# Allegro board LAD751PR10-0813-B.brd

Outline 338.42 x 185.75 mm; copper layers: TOP, GND1, IN1, GND2, IN2, GND3, IN3, IN4, GND4, IN5, GND5, IN6, GND6, BOTTOM. Coordinates in mm from the lower left corner of the outline.

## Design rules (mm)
net group CSO_1: nets CSON_1 CSOP_1
net group CSS_2: nets CSSN_2 CSSP_2
net group CSS_B+: nets CSSN_B+ CSSP_B+
net group CSSUM: nets CSNSUM CSPSUM
net group DDR-ALERT: nets DDR_A_ALERT# DDR_B_ALERT#
net group DDRB-CLK: nets M_CLK_DDR2 M_CLK_DDR#2
net group DIFFPAIR29: nets FBB_CLK0 FBB_CLK0#
net group DIFFPAIR50: nets M_CLK_DDR3 M_CLK_DDR#3
net group DIFFPAIR70: nets CSSN_1 CSSP_1
net group DIFFPAIR85: nets TP_CLK TP_DATA
net group DIFFPAIR150: nets HDMI_CTRLCLK HDMI_CTRLDAT
net group DIFFPAIR158: nets FBA_WCK45 FBA_WCK45#
net group DIFFPAIR159: nets FBA_WCK67 FBA_WCK67#
net group DIFFPAIR160: nets FBA_WCK23 FBA_WCK23#
net group DIFFPAIR161: nets FBA_WCK01 FBA_WCK01#
net group DIFFPAIR162: nets FBB_WCK45 FBB_WCK45#
net group DIFFPAIR163: nets FBB_WCK67 FBB_WCK67#
net group DIFFPAIR164: nets FBB_WCK23 FBB_WCK23#
net group DIFFPAIR165: nets FBB_WCK01 FBB_WCK01#
net group DIFFPAIR166: nets FBC_WCK45 FBC_WCK45#
net group DIFFPAIR167: nets FBC_WCK67 FBC_WCK67#
net group DIFFPAIR168: nets FBC_WCK23 FBC_WCK23#
net group DIFFPAIR169: nets FBC_WCK01 FBC_WCK01#
net group DIFFPAIR170: nets FBD_WCK45 FBD_WCK45#
net group DIFFPAIR171: nets FBD_WCK67 FBD_WCK67#
net group DIFFPAIR172: nets FBD_WCK01 FBD_WCK01#
net group DIFFPAIR173: nets FBD_WCK23 FBD_WCK23#
net group DIFFPAIR174: nets CPU_EDP_TX3N CPU_EDP_TX3P
net group DIFFPAIR175: nets CPU_EDP_TX2N CPU_EDP_TX2P
net group DIFFPAIR176: nets VGA_SMB_CK2 VGA_SMB_DA2
net group DIFFPAIR178: nets USB20_N9 USB20_P9
net group DIFFPAIR179: nets USB20_N9_L USB20_P9_L
net group DIFFPAIR180: nets TBTA_LSRX TBTA_LSTX
net group DIFFPAIR181: nets XTALIN XTALOUT
net group DIFFPAIR182: nets MDP_AUX#_SDA MDP_AUX_SCL
net group DIFFPAIR183: nets PCIE_PTX_DRX_N19_C PCIE_PTX_DRX_P19_C
net group DIFFPAIR184: nets PCIE_PTX_DRX_N20_C PCIE_PTX_DRX_P20_C
net group DIFFPAIR185: nets PCIE_PTX_DRX_N18_C PCIE_PTX_DRX_P18_C
net group DIFFPAIR186: nets PCIE_PTX_DRX_N13_C PCIE_PTX_DRX_P13_C
net group DIFFPAIR187: nets PCIE_PTX_DRX_N14_C PCIE_PTX_DRX_P14_C
net group DIFFPAIR188: nets PCIE_PTX_DRX_N11_C PCIE_PTX_DRX_P11_C
net group DIFFPAIR189: nets PCIE_PTX_DRX_N10_C PCIE_PTX_DRX_P10_C
net group DIFFPAIR190: nets PCIE_PTX_DRX_N12_C PCIE_PTX_DRX_P12_C
net group DIFFPAIR191: nets PCIE_PTX_DRX_N9_C PCIE_PTX_DRX_P9_C
net group DIFFPAIR192: nets PCIE_PTX_DRX_N17_C PCIE_PTX_DRX_P17_C
net group DP18: nets FBA_CLK1 FBA_CLK1#
net group FBA-CLK: nets FBA_CLK0 FBA_CLK0#
net group FBB-CLK: nets FBB_CLK1 FBB_CLK1#
net group FBC-CLK: nets FBC_CLK0 FBC_CLK0#
net group FBC_CLK1: nets FBC_CLK1 FBC_CLK1#
net group I2C0__EC: nets I2C0_SCL_EC I2C0_SDA_EC
net group I2CC_: nets I2CC_SCL I2CC_SDA
net group I2CC__R: nets I2CC_SCL_R I2CC_SDA_R
net group ISUM_GT: nets ISUMN_GT ISUMP_GT
net group ISUM_SA: nets ISUMN_SA ISUMP_SA
net group ISUM_VCORE: nets ISUMN_VCORE ISUMP_VCORE
net group NVVDD_ISUM1: nets NVVDD_ISUMN1 NVVDD_ISUMP1
net group NVVDD_ISUM2: nets NVVDD_ISUMN2 NVVDD_ISUMP2
net group NVVDD_ISUM3: nets NVVDD_ISUMN3 NVVDD_ISUMP3
net group NVVDD_ISUM4: nets NVVDD_ISUMN4 NVVDD_ISUMP4
net group PCIE_PRX_DTX_13: nets PCIE_PRX_DTX_N13 PCIE_PRX_DTX_P13
net group PCIE_PRX_DTX_14: nets PCIE_PRX_DTX_N14 PCIE_PRX_DTX_P14
net group PCIE_PTX_DRX_13: nets PCIE_PTX_DRX_N13 PCIE_PTX_DRX_P13
net group PCIE_PTX_DRX_14: nets PCIE_PTX_DRX_N14 PCIE_PTX_DRX_P14
net group SATA_PRX_DTX_3: nets SATA_PRX_DTX_N3 SATA_PRX_DTX_P3
net group SATA_PTX_DRX_3: nets SATA_PTX_DRX_N3 SATA_PTX_DRX_P3
net group SPK_L_CONN: nets SPK_L+_CONN SPK_L-_CONN
net group SPK_R_CONN: nets SPK_R+_CONN SPK_R-_CONN
net group TMDS_F: nets TMDS_SCLF TMDS_SDAF
net group USB3R3_C: nets USB3RN3_C USB3RP3_C
net group VIN1: nets VIN1N VIN1P
net group VIN2: nets VIN2N VIN2P
net group VIN3: nets VIN3N VIN3P
net group 12: nets DGPU_PEX_RST#
net group ASYNCHRONOUS: nets CALDERA_RST# CDRA_RST# CFG0 CFG1 CFG2 CFG3 CFG4 CFG5 CFG6 CFG7 CFG8 CFG9 CFG10 CFG11 CFG12 CFG13 CFG14 CFG15 CFG16 CFG17 CFG18 CFG19 CFG_RCOMP CPU_TRIGGER DDR4_DRAMRST# DGPU_HOLD_RST# DGPU_PEX_RST#_R DGPU_PWROK EDP_RCOMP GPU_PEX_RST_HOLD# H_CPUPWRGD H_DRAMRST# H_PECI H_PM_DOWN H_PM_SYNC_R H_PROCHOT# H_THERMTRIP# H_THERMTRIP#_R H_VCCST_PWRGD IMVP_VR_ON PCH_AZ_RST# PCH_DPWROK PCH_JTAG_TCK PCH_PECI PCH_PLTRST# PCH_PWR_EN PCH_PWROK PCH_SYS_PWROK_XDP PCH_TRIGGER PCIECOMP PCIECOMP# PECI_KB9012 PEG_RCOMP PLTRST_CPU# SLP_S3 SLP_S5 SUSACK# SUSP# SYS_PEX_RST_MON# SYS_PWROK SYS_RESET# SYSON TBT_RST#_R USB2_COMP USB_OC0# USB_OC2# VCCIO_PGOOD VR_HOT# VR_SVID_ALERT# VR_SVID_CLK VR_SVID_DATA XDP_BPM#0 XDP_BPM#1 XDP_PRDY# XDP_PREQ#
net group CODEC: nets HP2_D_L_C HP2_D_L_R HP2_D_R_C HP2_D_R_R HPOUT-L HPOUT-R
net group CRITICAL LOW SPEED: nets INTRUDER# PBTN_OUT# PCH_RTCRST# PCH_SRTCRST# PCIE_WAKE# WAKE#
net group CRYSTAL: nets PCH_RTCX1 PCH_RTCX2 TBT_XTAL_25_IN TBT_XTAL_25_OUT XTAL24_IN XTAL24_OUT XTLI XTLO
net group DDR-RCOMP: nets DDR_RCOMP0 DDR_RCOMP1 DDR_RCOMP2
net group DDRA-CLK: nets M_CLK_DDR0 M_CLK_DDR1 M_CLK_DDR#0 M_CLK_DDR#1
net group DDRA-CMD: nets DDR_A_BG0 DDR_A_BG1 DDR_A_BS0 DDR_A_BS1 DDR_A_CAS# DDR_A_MA0 DDR_A_MA1 DDR_A_MA2 DDR_A_MA3 DDR_A_MA4 DDR_A_MA5 DDR_A_MA6 DDR_A_MA7 DDR_A_MA8 DDR_A_MA9 DDR_A_MA10 DDR_A_MA11 DDR_A_MA12 DDR_A_MA13 DDR_A_RAS# DDR_A_WE#
net group DDRA-CTL: nets DDR_A_ACT# DDR_A_PAR DDR_CKE0_DIMMA DDR_CKE1_DIMMA DDR_CS0_DIMMA# DDR_CS1_DIMMA# M_ODT0 M_ODT1
net group DDRA-D0: nets DDR_A_D0 DDR_A_D1 DDR_A_D2 DDR_A_D3 DDR_A_D4 DDR_A_D5 DDR_A_D6 DDR_A_D7
net group DDRA-D1: nets DDR_A_D8 DDR_A_D9 DDR_A_D10 DDR_A_D11 DDR_A_D12 DDR_A_D13 DDR_A_D14 DDR_A_D15
net group DDRA-D2: nets DDR_A_D16 DDR_A_D17 DDR_A_D18 DDR_A_D19 DDR_A_D20 DDR_A_D21 DDR_A_D22 DDR_A_D23
net group DDRA-D3: nets DDR_A_D24 DDR_A_D25 DDR_A_D26 DDR_A_D27 DDR_A_D28 DDR_A_D29 DDR_A_D30 DDR_A_D31
net group DDRA-D4: nets DDR_A_D32 DDR_A_D33 DDR_A_D34 DDR_A_D35 DDR_A_D36 DDR_A_D37 DDR_A_D38 DDR_A_D39
net group DDRA-D5: nets DDR_A_D40 DDR_A_D41 DDR_A_D42 DDR_A_D43 DDR_A_D44 DDR_A_D45 DDR_A_D46 DDR_A_D47
net group DDRA-D6: nets DDR_A_D48 DDR_A_D49 DDR_A_D50 DDR_A_D51 DDR_A_D52 DDR_A_D53 DDR_A_D54 DDR_A_D55
net group DDRA-D7: nets DDR_A_D56 DDR_A_D57 DDR_A_D58 DDR_A_D59 DDR_A_D60 DDR_A_D61 DDR_A_D62 DDR_A_D63
net group DDRA-DQS: nets DDR_A_DQS0 DDR_A_DQS1 DDR_A_DQS2 DDR_A_DQS3 DDR_A_DQS4 DDR_A_DQS5 DDR_A_DQS6 DDR_A_DQS7 DDR_A_DQS#0 DDR_A_DQS#1 DDR_A_DQS#2 DDR_A_DQS#3 DDR_A_DQS#4 DDR_A_DQS#5 DDR_A_DQS#6 DDR_A_DQS#7
net group DDRB-CMD: nets DDR_B_BG0 DDR_B_BG1 DDR_B_BS0 DDR_B_BS1 DDR_B_CAS# DDR_B_MA0 DDR_B_MA1 DDR_B_MA2 DDR_B_MA3 DDR_B_MA4 DDR_B_MA5 DDR_B_MA6 DDR_B_MA7 DDR_B_MA8 DDR_B_MA9 DDR_B_MA10 DDR_B_MA11 DDR_B_MA12 DDR_B_MA13 DDR_B_RAS# DDR_B_WE#
net group DDRB-CTL: nets DDR_B_ACT# DDR_B_PAR DDR_CKE2_DIMMB DDR_CKE3_DIMMB DDR_CS2_DIMMB# DDR_CS3_DIMMB# M_ODT2 M_ODT3
net group DDRB-D0: nets DDR_B_D0 DDR_B_D1 DDR_B_D2 DDR_B_D3 DDR_B_D4 DDR_B_D5 DDR_B_D6 DDR_B_D7
net group DDRB-D1: nets DDR_B_D8 DDR_B_D9 DDR_B_D10 DDR_B_D11 DDR_B_D12 DDR_B_D13 DDR_B_D14 DDR_B_D15
net group DDRB-D2: nets DDR_B_D16 DDR_B_D17 DDR_B_D18 DDR_B_D19 DDR_B_D20 DDR_B_D21 DDR_B_D22 DDR_B_D23
net group DDRB-D3: nets DDR_B_D24 DDR_B_D25 DDR_B_D26 DDR_B_D27 DDR_B_D28 DDR_B_D29 DDR_B_D30 DDR_B_D31
net group DDRB-D4: nets DDR_B_D32 DDR_B_D33 DDR_B_D34 DDR_B_D35 DDR_B_D36 DDR_B_D37 DDR_B_D38 DDR_B_D39
net group DDRB-D5: nets DDR_B_D40 DDR_B_D41 DDR_B_D42 DDR_B_D43 DDR_B_D44 DDR_B_D45 DDR_B_D46 DDR_B_D47
net group DDRB-D6: nets DDR_B_D48 DDR_B_D49 DDR_B_D50 DDR_B_D51 DDR_B_D52 DDR_B_D53 DDR_B_D54 DDR_B_D55
net group DDRB-D7: nets DDR_B_D56 DDR_B_D57 DDR_B_D58 DDR_B_D59 DDR_B_D60 DDR_B_D61 DDR_B_D62 DDR_B_D63
net group DDRB-DQS: nets DDR_B_DQS0 DDR_B_DQS1 DDR_B_DQS2 DDR_B_DQS3 DDR_B_DQS4 DDR_B_DQS5 DDR_B_DQS6 DDR_B_DQS7 DDR_B_DQS#0 DDR_B_DQS#1 DDR_B_DQS#2 DDR_B_DQS#3 DDR_B_DQS#4 DDR_B_DQS#5 DDR_B_DQS#6 DDR_B_DQS#7
net group DIFFPAIR148: nets REMOTE3-
net group DMI: nets DMI_CRX_PTX_N0 DMI_CRX_PTX_N1 DMI_CRX_PTX_N2 DMI_CRX_PTX_N3 DMI_CRX_PTX_P0 DMI_CRX_PTX_P1 DMI_CRX_PTX_P2 DMI_CRX_PTX_P3 DMI_CTX_PRX_N0 DMI_CTX_PRX_N1 DMI_CTX_PRX_N2 DMI_CTX_PRX_N3 DMI_CTX_PRX_P0 DMI_CTX_PRX_P1 DMI_CTX_PRX_P2 DMI_CTX_PRX_P3 DMIC_CLK1_R DMIC_DATA1_R
net group DP: nets CPU_DDC1CLK CPU_DDC1DATA CPU_DDC2CLK CPU_DDC2DATA CPU_DP1_AUXN CPU_DP1_AUXN_C CPU_DP1_AUXP CPU_DP1_AUXP_C CPU_DP1_N0 CPU_DP1_N0_C CPU_DP1_N1 CPU_DP1_N1_C CPU_DP1_N2 CPU_DP1_N2_C CPU_DP1_N3 CPU_DP1_N3_C CPU_DP1_P0 CPU_DP1_P0_C CPU_DP1_P1 CPU_DP1_P1_C CPU_DP1_P2 CPU_DP1_P2_C CPU_DP1_P3 CPU_DP1_P3_C CPU_DP2_AUXN CPU_DP2_AUXN_C CPU_DP2_AUXP CPU_DP2_AUXP_C CPU_DP2_N0 CPU_DP2_N0_C CPU_DP2_N1 CPU_DP2_N1_C CPU_DP2_N2 CPU_DP2_N2_C CPU_DP2_N3 CPU_DP2_N3_C CPU_DP2_P0 CPU_DP2_P0_C CPU_DP2_P1 CPU_DP2_P1_C CPU_DP2_P2 CPU_DP2_P2_C CPU_DP2_P3 CPU_DP2_P3_C
net group EDP-CPU: nets CPU_EDP_AUX CPU_EDP_AUX# CPU_EDP_AUX#_C CPU_EDP_AUX_C CPU_EDP_N0_C CPU_EDP_N1_C CPU_EDP_N2_C CPU_EDP_N3_C CPU_EDP_P0_C CPU_EDP_P1_C CPU_EDP_P2_C CPU_EDP_P3_C CPU_EDP_TX0N CPU_EDP_TX0P CPU_EDP_TX1N CPU_EDP_TX1P
net group EDP-GPU: nets GPU_AUXN/DDC GPU_AUXN/DDC_C GPU_AUXP/DDC GPU_AUXP/DDC_C GPU_TX0N GPU_TX0N_C GPU_TX0P GPU_TX0P_C GPU_TX1N GPU_TX1N_C GPU_TX1P GPU_TX1P_C GPU_TX2N GPU_TX2N_C GPU_TX2P GPU_TX2P_C GPU_TX3N GPU_TX3N_C GPU_TX3P GPU_TX3P_C
net group EDP-MUX: nets EDP_AUX#_C EDP_AUX_C EDP_TX0#_C EDP_TX0_C EDP_TX1#_C EDP_TX1_C EDP_TX2#_C EDP_TX2_C EDP_TX3#_C EDP_TX3_C MUX_EDP_A0N MUX_EDP_A0P MUX_EDP_A1N MUX_EDP_A1P MUX_EDP_A2N MUX_EDP_A2P MUX_EDP_A3N MUX_EDP_A3P MUX_EDP_AUXN MUX_EDP_AUXP
net group EMC: nets BOOT_1.2V BST_1.2V BST_3V BST_5V CPU_XDP_TRST# MIC_CLK MIC_DATA RJ45_CT0 RJ45_CT1 RJ45_CT2 RJ45_CT3 TBT_TCK
net group FBA-CMD: nets FBA_CMD0 FBA_CMD1 FBA_CMD2 FBA_CMD3 FBA_CMD4 FBA_CMD5 FBA_CMD6 FBA_CMD7 FBA_CMD8 FBA_CMD9 FBA_CMD10 FBA_CMD11 FBA_CMD12 FBA_CMD13 FBA_CMD14 FBA_CMD15 FBA_CMD16 FBA_CMD17 FBA_CMD18 FBA_CMD19 FBA_CMD20 FBA_CMD21 FBA_CMD22 FBA_CMD23 FBA_CMD24 FBA_CMD25 FBA_CMD26 FBA_CMD27 FBA_CMD28 FBA_CMD29 FBA_CMD30 FBA_CMD31
net group FBA-D0: nets FBA_D0 FBA_D1 FBA_D2 FBA_D3 FBA_D4 FBA_D5 FBA_D6 FBA_D7
net group FBA-D1: nets FBA_D8 FBA_D9 FBA_D10 FBA_D11 FBA_D12 FBA_D13 FBA_D14 FBA_D15
net group FBA-D2: nets FBA_D16 FBA_D17 FBA_D18 FBA_D19 FBA_D20 FBA_D21 FBA_D22 FBA_D23
net group FBA-D3: nets FBA_D24 FBA_D25 FBA_D26 FBA_D27 FBA_D28 FBA_D29 FBA_D30 FBA_D31
net group FBA-D4: nets FBA_D32 FBA_D33 FBA_D34 FBA_D35 FBA_D36 FBA_D37 FBA_D38 FBA_D39
net group FBA-D5: nets FBA_D40 FBA_D41 FBA_D42 FBA_D43 FBA_D44 FBA_D45 FBA_D46 FBA_D47
net group FBA-D6: nets FBA_D48 FBA_D49 FBA_D50 FBA_D51 FBA_D52 FBA_D53 FBA_D54 FBA_D55
net group FBA-D7: nets FBA_D56 FBA_D57 FBA_D58 FBA_D59 FBA_D60 FBA_D61 FBA_D62 FBA_D63
net group FBA-DBI: nets FBA_DBI0 FBA_DBI1 FBA_DBI2 FBA_DBI3 FBA_DBI4 FBA_DBI5 FBA_DBI6 FBA_DBI7
net group FBA-EDC: nets FBA_EDC0 FBA_EDC1 FBA_EDC2 FBA_EDC3 FBA_EDC4 FBA_EDC5 FBA_EDC6 FBA_EDC7
net group FBB-CMD: nets FBB_CMD0 FBB_CMD1 FBB_CMD2 FBB_CMD3 FBB_CMD4 FBB_CMD5 FBB_CMD6 FBB_CMD7 FBB_CMD8 FBB_CMD9 FBB_CMD10 FBB_CMD11 FBB_CMD12 FBB_CMD13 FBB_CMD14 FBB_CMD15 FBB_CMD16 FBB_CMD17 FBB_CMD18 FBB_CMD19 FBB_CMD20 FBB_CMD21 FBB_CMD22 FBB_CMD23 FBB_CMD24 FBB_CMD25 FBB_CMD26 FBB_CMD27 FBB_CMD28 FBB_CMD29 FBB_CMD30 FBB_CMD31
net group FBB-D0: nets FBB_D0 FBB_D1 FBB_D2 FBB_D3 FBB_D4 FBB_D5 FBB_D6 FBB_D7
net group FBB-D1: nets FBB_D8 FBB_D9 FBB_D10 FBB_D11 FBB_D12 FBB_D13 FBB_D14 FBB_D15
net group FBB-D2: nets FBB_D16 FBB_D17 FBB_D18 FBB_D19 FBB_D20 FBB_D21 FBB_D22 FBB_D23
net group FBB-D3: nets FBB_D24 FBB_D25 FBB_D26 FBB_D27 FBB_D28 FBB_D29 FBB_D30 FBB_D31
net group FBB-D4: nets FBB_D32 FBB_D33 FBB_D34 FBB_D35 FBB_D36 FBB_D37 FBB_D38 FBB_D39
net group FBB-D5: nets FBB_D40 FBB_D41 FBB_D42 FBB_D43 FBB_D44 FBB_D45 FBB_D46 FBB_D47
net group FBB-D6: nets FBB_D48 FBB_D49 FBB_D50 FBB_D51 FBB_D52 FBB_D53 FBB_D54 FBB_D55
net group FBB-D7: nets FBB_D56 FBB_D57 FBB_D58 FBB_D59 FBB_D60 FBB_D61 FBB_D62 FBB_D63
net group FBB-DBI: nets FBB_DBI0 FBB_DBI1 FBB_DBI2 FBB_DBI3 FBB_DBI4 FBB_DBI5 FBB_DBI6 FBB_DBI7
net group FBB-EDC: nets FBB_EDC0 FBB_EDC1 FBB_EDC2 FBB_EDC3 FBB_EDC4 FBB_EDC5 FBB_EDC6 FBB_EDC7
net group FBC-CMD: nets FBC_CMD0 FBC_CMD1 FBC_CMD2 FBC_CMD3 FBC_CMD4 FBC_CMD5 FBC_CMD6 FBC_CMD7 FBC_CMD8 FBC_CMD9 FBC_CMD10 FBC_CMD11 FBC_CMD12 FBC_CMD13 FBC_CMD14 FBC_CMD15 FBC_CMD16 FBC_CMD17 FBC_CMD18 FBC_CMD19 FBC_CMD20 FBC_CMD21 FBC_CMD22 FBC_CMD23 FBC_CMD24 FBC_CMD25 FBC_CMD26 FBC_CMD27 FBC_CMD28 FBC_CMD29 FBC_CMD30 FBC_CMD31
net group FBC-D0: nets FBC_D0 FBC_D1 FBC_D2 FBC_D3 FBC_D4 FBC_D5 FBC_D6 FBC_D7
net group FBC-D1: nets FBC_D8 FBC_D9 FBC_D10 FBC_D11 FBC_D12 FBC_D13 FBC_D14 FBC_D15
net group FBC-D2: nets FBC_D16 FBC_D17 FBC_D18 FBC_D19 FBC_D20 FBC_D21 FBC_D22 FBC_D23
net group FBC-D3: nets FBC_D24 FBC_D25 FBC_D26 FBC_D27 FBC_D28 FBC_D29 FBC_D30 FBC_D31
net group FBC-D4: nets FBC_D32 FBC_D33 FBC_D34 FBC_D35 FBC_D36 FBC_D37 FBC_D38 FBC_D39
net group FBC-D5: nets FBC_D40 FBC_D41 FBC_D42 FBC_D43 FBC_D44 FBC_D45 FBC_D46 FBC_D47
net group FBC-D6: nets FBC_D48 FBC_D49 FBC_D50 FBC_D51 FBC_D52 FBC_D53 FBC_D54 FBC_D55
net group FBC-D7: nets FBC_D56 FBC_D57 FBC_D58 FBC_D59 FBC_D60 FBC_D61 FBC_D62 FBC_D63
net group FBC-DBI: nets FBC_DBI0 FBC_DBI1 FBC_DBI2 FBC_DBI3 FBC_DBI4 FBC_DBI5 FBC_DBI6 FBC_DBI7
net group FBC-EDC: nets FBC_EDC0 FBC_EDC1 FBC_EDC2 FBC_EDC3 FBC_EDC4 FBC_EDC5 FBC_EDC6 FBC_EDC7
net group FBD-CLK: nets FBD_CLK0 FBD_CLK0# FBD_CLK1 FBD_CLK1#
net group FBD-CMD: nets FBD_CMD0 FBD_CMD1 FBD_CMD2 FBD_CMD3 FBD_CMD4 FBD_CMD5 FBD_CMD6 FBD_CMD7 FBD_CMD8 FBD_CMD9 FBD_CMD10 FBD_CMD11 FBD_CMD12 FBD_CMD13 FBD_CMD14 FBD_CMD15 FBD_CMD16 FBD_CMD17 FBD_CMD18 FBD_CMD19 FBD_CMD20 FBD_CMD21 FBD_CMD22 FBD_CMD23 FBD_CMD24 FBD_CMD25 FBD_CMD26 FBD_CMD27 FBD_CMD28 FBD_CMD29 FBD_CMD30 FBD_CMD31
net group FBD-D0: nets FBD_D0 FBD_D1 FBD_D2 FBD_D3 FBD_D4 FBD_D5 FBD_D6 FBD_D7
net group FBD-D1: nets FBD_D8 FBD_D9 FBD_D10 FBD_D11 FBD_D12 FBD_D13 FBD_D14 FBD_D15
net group FBD-D2: nets FBD_D16 FBD_D17 FBD_D18 FBD_D19 FBD_D20 FBD_D21 FBD_D22 FBD_D23
net group FBD-D3: nets FBD_D24 FBD_D25 FBD_D26 FBD_D27 FBD_D28 FBD_D29 FBD_D30 FBD_D31
net group FBD-D4: nets FBD_D32 FBD_D33 FBD_D34 FBD_D35 FBD_D36 FBD_D37 FBD_D38 FBD_D39
net group FBD-D5: nets FBD_D40 FBD_D41 FBD_D42 FBD_D43 FBD_D44 FBD_D45 FBD_D46 FBD_D47
net group FBD-D6: nets FBD_D48 FBD_D49 FBD_D50 FBD_D51 FBD_D52 FBD_D53 FBD_D54 FBD_D55
net group FBD-D7: nets FBD_D56 FBD_D57 FBD_D58 FBD_D59 FBD_D60 FBD_D61 FBD_D62 FBD_D63
net group FBD-DBI: nets FBD_DBI0 FBD_DBI1 FBD_DBI2 FBD_DBI3 FBD_DBI4 FBD_DBI5 FBD_DBI6 FBD_DBI7
net group FBD-EDC: nets FBD_EDC0 FBD_EDC1 FBD_EDC2 FBD_EDC3 FBD_EDC4 FBD_EDC5 FBD_EDC6 FBD_EDC7
net group HDA: nets HDA_SPKR ME_EN N19501610 PCH_AZ_BITCLK PCH_AZ_CODEC_BITCLK PCH_AZ_CODEC_RST# PCH_AZ_CODEC_RST#_R PCH_AZ_CODEC_SDIN0 PCH_AZ_CODEC_SDOUT PCH_AZ_CODEC_SYNC PCH_AZ_SDOUT PCH_AZ_SYNC
net group HDMI: nets TMDS_C_TX0N TMDS_C_TX0P TMDS_C_TX1N TMDS_C_TX1P TMDS_C_TX2N TMDS_C_TX2P TMDS_C_TXCN TMDS_C_TXCP TMDS_CTRLCLK_R TMDS_CTRLDAT_R TMDS_R_TX0N TMDS_R_TX0P TMDS_R_TX1N TMDS_R_TX1P TMDS_R_TX2N TMDS_R_TX2P TMDS_R_TXCN TMDS_R_TXCP TMDS_TX0N TMDS_TX0P TMDS_TX1N TMDS_TX1P TMDS_TX2N TMDS_TX2P TMDS_TXCN TMDS_TXCP
net group I2C: nets I2C_CLK I2C_DAT TBT_I2C_SCL TBT_I2C_SDA TBTA_I2C_INT TBTA_I2C_SCL1_R TBTA_I2C_SDA1_R TBTB_I2C_INT
net group LAN: nets LAN_MDIN0 LAN_MDIN1 LAN_MDIN2 LAN_MDIN3 LAN_MDIP0 LAN_MDIP1 LAN_MDIP2 LAN_MDIP3
net group LAN(NO_REF): nets RJ45_MDI0+ RJ45_MDI0- RJ45_MDI1+ RJ45_MDI1- RJ45_MDI2+ RJ45_MDI2- RJ45_MDI3+ RJ45_MDI3-
net group LPC: nets LPC_AD0 LPC_AD1 LPC_AD2 LPC_AD3 LPC_FRAME#
net group MDP: nets DISP_CLK_AUXP_CONN GPU_MDP_N0 GPU_MDP_N1 GPU_MDP_N2 GPU_MDP_N3 GPU_MDP_P0 GPU_MDP_P1 GPU_MDP_P2 GPU_MDP_P3 MDP_LANE_N0_C MDP_LANE_N1_C MDP_LANE_N2_C MDP_LANE_N3_C MDP_LANE_P0_C MDP_LANE_P1_C MDP_LANE_P2_C MDP_LANE_P3_C
net group PCIE: nets PCIE_PRX_DTX_N5 PCIE_PRX_DTX_N5_C PCIE_PRX_DTX_N6 PCIE_PRX_DTX_N9 PCIE_PRX_DTX_N10 PCIE_PRX_DTX_N11 PCIE_PRX_DTX_N12 PCIE_PRX_DTX_N17 PCIE_PRX_DTX_N18 PCIE_PRX_DTX_N19 PCIE_PRX_DTX_N20 PCIE_PRX_DTX_P5 PCIE_PRX_DTX_P5_C PCIE_PRX_DTX_P6 PCIE_PRX_DTX_P9 PCIE_PRX_DTX_P10 PCIE_PRX_DTX_P11 PCIE_PRX_DTX_P12 PCIE_PRX_DTX_P17 PCIE_PRX_DTX_P18 PCIE_PRX_DTX_P19 PCIE_PRX_DTX_P20 PCIE_PTX_DRX_N5 PCIE_PTX_DRX_N5_C PCIE_PTX_DRX_N6 PCIE_PTX_DRX_N6_C PCIE_PTX_DRX_N9 PCIE_PTX_DRX_N10 PCIE_PTX_DRX_N11 PCIE_PTX_DRX_N12 PCIE_PTX_DRX_N17 PCIE_PTX_DRX_N18 PCIE_PTX_DRX_N19 PCIE_PTX_DRX_N20 PCIE_PTX_DRX_P5 PCIE_PTX_DRX_P5_C PCIE_PTX_DRX_P6 PCIE_PTX_DRX_P6_C PCIE_PTX_DRX_P9 PCIE_PTX_DRX_P10 PCIE_PTX_DRX_P11 PCIE_PTX_DRX_P12 PCIE_PTX_DRX_P17 PCIE_PTX_DRX_P18 PCIE_PTX_DRX_P19 PCIE_PTX_DRX_P20
net group PEG: nets CRX_N8 CRX_N9 CRX_N10 CRX_N11 CRX_P8 CRX_P9 CRX_P10 CRX_P11 PEG_CRX_C_GTX_N8 PEG_CRX_C_GTX_N9 PEG_CRX_C_GTX_N10 PEG_CRX_C_GTX_N11 PEG_CRX_C_GTX_P8 PEG_CRX_C_GTX_P9 PEG_CRX_C_GTX_P10 PEG_CRX_C_GTX_P11 PEG_CRX_GTX_N0 PEG_CRX_GTX_N0_C PEG_CRX_GTX_N1 PEG_CRX_GTX_N1_C PEG_CRX_GTX_N2 PEG_CRX_GTX_N2_C PEG_CRX_GTX_N3 PEG_CRX_GTX_N3_C PEG_CRX_GTX_N4 PEG_CRX_GTX_N4_C PEG_CRX_GTX_N5 PEG_CRX_GTX_N5_C PEG_CRX_GTX_N6 PEG_CRX_GTX_N6_C PEG_CRX_GTX_N7 PEG_CRX_GTX_N7_C PEG_CRX_GTX_N8 PEG_CRX_GTX_N9 PEG_CRX_GTX_N10 PEG_CRX_GTX_N11 PEG_CRX_GTX_P0 PEG_CRX_GTX_P0_C PEG_CRX_GTX_P1 PEG_CRX_GTX_P1_C PEG_CRX_GTX_P2 PEG_CRX_GTX_P2_C PEG_CRX_GTX_P3 PEG_CRX_GTX_P3_C PEG_CRX_GTX_P4 PEG_CRX_GTX_P4_C PEG_CRX_GTX_P5 PEG_CRX_GTX_P5_C PEG_CRX_GTX_P6 PEG_CRX_GTX_P6_C PEG_CRX_GTX_P7 PEG_CRX_GTX_P7_C PEG_CRX_GTX_P8 PEG_CRX_GTX_P9 PEG_CRX_GTX_P10 PEG_CRX_GTX_P11 PEG_CRX_TTX_N12 PEG_CRX_TTX_N12_C PEG_CRX_TTX_N13 PEG_CRX_TTX_N13_C PEG_CRX_TTX_N14 PEG_CRX_TTX_N14_C PEG_CRX_TTX_N15 PEG_CRX_TTX_N15_C PEG_CRX_TTX_P12 PEG_CRX_TTX_P12_C PEG_CRX_TTX_P13 PEG_CRX_TTX_P13_C PEG_CRX_TTX_P14 PEG_CRX_TTX_P14_C PEG_CRX_TTX_P15 PEG_CRX_TTX_P15_C PEG_CTX_C_GRX_N0 PEG_CTX_C_GRX_N1 PEG_CTX_C_GRX_N2 PEG_CTX_C_GRX_N3 PEG_CTX_C_GRX_N4 PEG_CTX_C_GRX_N5 PEG_CTX_C_GRX_N6 PEG_CTX_C_GRX_N7 PEG_CTX_C_GRX_N8 PEG_CTX_C_GRX_N9 PEG_CTX_C_GRX_N10 PEG_CTX_C_GRX_N11 PEG_CTX_C_GRX_P0 PEG_CTX_C_GRX_P1 PEG_CTX_C_GRX_P2 PEG_CTX_C_GRX_P3 PEG_CTX_C_GRX_P4 PEG_CTX_C_GRX_P5 PEG_CTX_C_GRX_P6 PEG_CTX_C_GRX_P7 PEG_CTX_C_GRX_P8 PEG_CTX_C_GRX_P9 PEG_CTX_C_GRX_P10 PEG_CTX_C_GRX_P11 PEG_CTX_GRX_N0 PEG_CTX_GRX_N1 PEG_CTX_GRX_N2 PEG_CTX_GRX_N3 PEG_CTX_GRX_N4 PEG_CTX_GRX_N5 PEG_CTX_GRX_N6 PEG_CTX_GRX_N7 PEG_CTX_GRX_N8 PEG_CTX_GRX_N9 PEG_CTX_GRX_N10 PEG_CTX_GRX_N11 PEG_CTX_GRX_P0 PEG_CTX_GRX_P1 PEG_CTX_GRX_P2 PEG_CTX_GRX_P3 PEG_CTX_GRX_P4 PEG_CTX_GRX_P5 PEG_CTX_GRX_P6 PEG_CTX_GRX_P7 PEG_CTX_GRX_P8 PEG_CTX_GRX_P9 PEG_CTX_GRX_P10 PEG_CTX_GRX_P11 PEG_CTX_TRX_N12 PEG_CTX_TRX_N12_C PEG_CTX_TRX_N13 PEG_CTX_TRX_N13_C PEG_CTX_TRX_N14 PEG_CTX_TRX_N14_C PEG_CTX_TRX_N15 PEG_CTX_TRX_N15_C PEG_CTX_TRX_P12 PEG_CTX_TRX_P12_C PEG_CTX_TRX_P13 PEG_CTX_TRX_P13_C PEG_CTX_TRX_P14 PEG_CTX_TRX_P14_C PEG_CTX_TRX_P15 PEG_CTX_TRX_P15_C
net group PLATFORM-CLK: nets CLK_PCI_LPC CLK_PCIE_DGPU#_C CLK_PCIE_DGPU_C CLK_PCIE_N1 CLK_PCIE_N2 CLK_PCIE_N3 CLK_PCIE_N4 CLK_PCIE_N5 CLK_PCIE_N6 CLK_PCIE_N7 CLK_PCIE_P1 CLK_PCIE_P2 CLK_PCIE_P3 CLK_PCIE_P4 CLK_PCIE_P5 CLK_PCIE_P6 CLK_PCIE_P7 CLK_PEG_GPU CLK_PEG_GPU# CPU_24MHZ_N CPU_24MHZ_P PCH_CPU_BCLK_N PCH_CPU_BCLK_P PCH_CPU_PCIBCLK_N PCH_CPU_PCIBCLK_P PCH_XDP_CLK_N PCH_XDP_CLK_P
net group POWER: nets +0.6VS +0.6VSP +0.9V_CIO +0.9V_LVR_OUT +0.9V_SVR +0.9V_USB +1.2V_VCCPLL_OC +1.2VP +1.8VA_TBTA_LDO +1.8VD_TBTA_LDO +1V_MPHY +1V_PCH +1V_PCH_PRIM +1V_VCCDSW +1VALWP +1VALWP_B+ +1VALWP_PGOOD +2.5V_MEM +2.5V_MEMP +2.5VOUT +2.5VSP_ON +2.5VSP_VIN +3.3V_1.8V_DVDD +3.3V_1.8V_DVDD_IO +3.3V_ANA_PCIE +3.3V_ANA_USB2 +3.3V_F383 +3.3V_FLASH +3.3V_LC +3.3V_TBT_SX +3.3V_TBT_SX_R +3V_PCH +3VALW_PD +3VALWP +3VLP +3VS_CAM +3VS_DP +3VS_TBT +3VS_TOUCH +5V_PVDD +5V_TOBII +5V_USB_PWR1 +5V_USB_PWR2 +5V_USBC_VBUS +5VA +5VALW_LED +5VALWP +5VS_TP_LED +AVDDH +AVDDL +CODEC_AVDD2 +DVDDL +EC_VCCA +HDMI_5V_OUT +INV_PWR_SRC +LAN_IO +LCDVDD +PVDD +RBIAS +RTC_CELL +TBTA_VBUS +V18R +VCCIOP +VCCST +VCCSTG +VDD_TOUCH +VDDCT_L
net group SENSE: nets VCCGT_SENSE VCCIO_SENSE VCCSA_SENSE VCCSENSE VSSGT_SENSE VSSIO_SENSE VSSSA_SENSE VSSSENSE
net group SMBUS: nets CLK_SMB DAT_SMB EC_SMB_CK1 EC_SMB_CK2 EC_SMB_DA1 EC_SMB_DA2 IN1_PEQ# IN2_PEQ# PCH_SMBCLK PCH_SMBDATA SML0CLK SML0DATA SML1CLK SML1DATA
net group SPI: nets PCH_SPI_CLK PCH_SPI_CLK_R PCH_SPI_CS# PCH_SPI_HOLD# PCH_SPI_HOLD#_R PCH_SPI_SI PCH_SPI_SI_R PCH_SPI_SO PCH_SPI_SO_R PCH_SPI_WP# PCH_SPI_WP#_R PD_EE_CLK PD_EE_CS_N PD_EE_DI PD_EE_DO ROM_CS# ROM_SCLK ROM_SI ROM_SO SPI_MOCLK SPI_MOCS# SPI_MOSI SPI_MOSO TBT_EE_CLK TBT_EE_CS_N TBT_EE_DI TBT_EE_DO TBT_EE_WP_N
net group TBT: nets TBT_A_AUX_N TBT_A_AUX_N_C TBT_A_AUX_P TBT_A_AUX_P_C TBTA_DIG_AUD_N TBTA_DIG_AUD_P TBTA_SBU1 TBTA_SBU2
net group THERMAL: nets REMOTE1+ REMOTE1- REMOTE2+ REMOTE2- REMOTE3+
net group TMDS-MDP: nets DISP_DAT_AUXN_CONN DP_AUXN_C DP_AUXP_C GPU_DPC_AUX GPU_DPC_AUX#
net group USB20: nets SW_USB20_N1 SW_USB20_P1 TBT_A_USB20_L_NB TBT_A_USB20_L_NT TBT_A_USB20_L_PB TBT_A_USB20_L_PT TBT_A_USB20_N TBT_A_USB20_NB TBT_A_USB20_NT TBT_A_USB20_P TBT_A_USB20_PB TBT_A_USB20_PT USB3_CTX_C_DRX_N1 USB3_CTX_C_DRX_P1 USB3_CTX_C_L_DRX_N1 USB3_CTX_C_L_DRX_P1 USB3TN1 USB3TP1 USB20_CAM_N7_R USB20_CAM_P7_R USB20_N1 USB20_N1_CONN USB20_N2 USB20_N3 USB20_N3_CONN USB20_N4 USB20_N5 USB20_N6 USB20_N7 USB20_N8 USB20_N8_CONN USB20_P1 USB20_P1_CONN USB20_P2 USB20_P3 USB20_P3_CONN USB20_P4 USB20_P5 USB20_P6 USB20_P7 USB20_P8 USB20_P8_CONN
net group USB30: nets USB3_A_TRX_DTX_N0 USB3_A_TRX_DTX_N1 USB3_A_TRX_DTX_P0 USB3_A_TRX_DTX_P1 USB3_A_TTX_C_DRX_N0 USB3_A_TTX_C_DRX_N1 USB3_A_TTX_C_DRX_P0 USB3_A_TTX_C_DRX_P1 USB3_A_TTX_DRX_N0 USB3_A_TTX_DRX_N1 USB3_A_TTX_DRX_P0 USB3_A_TTX_DRX_P1 USB3_CRX_L_DTX_N1 USB3_CRX_L_DTX_N2 USB3_CRX_L_DTX_N5 USB3_CRX_L_DTX_P1 USB3_CRX_L_DTX_P2 USB3_CRX_L_DTX_P5 USB3_CTX_C_DRX_N2 USB3_CTX_C_DRX_N5 USB3_CTX_C_DRX_P2 USB3_CTX_C_DRX_P5 USB3_CTX_C_L_DRX_N2 USB3_CTX_C_L_DRX_N5 USB3_CTX_C_L_DRX_P2 USB3_CTX_C_L_DRX_P5 USB3RN1 USB3RN2 USB3RN3 USB3RN4 USB3RN5 USB3RP1 USB3RP2 USB3RP3 USB3RP4 USB3RP5 USB3TN2 USB3TN3 USB3TN4 USB3TN5 USB3TP2 USB3TP3 USB3TP4 USB3TP5
net group VREF: nets +V_DDR_REFA +V_DDR_REFA_R +V_DDR_REFB +V_DDR_REFB_R
net group XDP: nets XDP_TMS
nets with their own width: min track width 0.127; nets TP_LED_EN
nets with their own width: min track width 0.254; nets ECAGND
nets with their own width: min track width 0.381; nets TBTA_CC1 TBTA_CC2
nets with their own width: min track width 0.508; nets +0.9V_DP +0.9V_PCIE +1.2V_DDR +1VALW +3VALW +3VS +5VALW +5VS +VCC_CORE +VCCGT +VCCIO +VCCSA ALIEN_LED_B_DRV# ALIEN_LED_G_DRV# ALIEN_LED_R_DRV# B+ B+_BIAS BATT_CHG_LED BATT_CHG_LED# BATT_LOW_LED BATT_LOW_LED# EN_TPLED GND GNDA LAN_LED2# LAN_LED2#_R LOGO_LED_B_DRV# LOGO_LED_G_DRV# LOGO_LED_R_DRV# N21000719 N124752685 N124753277 POK POWER_LED PWR_B_7313# PWR_G_7313# PWR_LED# PWR_R_7313# TP_LED_B# TP_LED_G# TP_LED_R# VSB_N_001 VSB_N_002 VSB_N_003 XCLK_BIASREF
nets with their own width: min track width 1.016; nets ISENSEP_L ISENSEP_L_R ISENSEP_R ISENSEP_R_R IVSENSE_L IVSENSE_R LINE1_L LINE1_R RJ45_CT VSENSEN_L VSENSEN_R
nets with their own width: min track width 1.524; nets +5V_HDD

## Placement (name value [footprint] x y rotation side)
C2  0.1U_0402_10V6K  [C_0402]  192.4 14.51 0 bottom
C3  2200P_0402_25V7K  [C_0402]  128.04 101.48 180 bottom
C4  1U_0402_6.3V6K  [C_0402]  177.43 74.47 270 top
C6  0.1U_0402_10V7K  [C_0402]  178.42 82.37 0 top
C7  1U_0402_6.3V6K  [C_0402]  182.04 77.22 0 top
C10  0.1U_0402_10V7K  [C_0402]  181.54 82.33 0 top
C11  0.1U_0402_10V7K  [C_0402]  130 102.15 270 bottom
C29  0.1U_0402_16V4Z  [C_0402]  193.25 12.92 180 top
C256  10U_0402_6.3V6M  [C_0402]  58.09 9.66 180 bottom
C257  10U_0603_6.3V6M  [C_0603]  58.29 10.73 180 bottom
C258  0.1U_0402_16V7K  [C_0402]  65.39 16.92 90 bottom
C260  10U_0402_6.3V6M  [C_0402]  72.13 11.67 0 bottom
C261  10U_0603_6.3V6M  [C_0603]  71.6 10.61 0 bottom
C262  10U_0603_6.3V6M  [C_0603]  67.61 17.21 0 bottom
C263  0.1U_0402_10V7K  [C_0402]  67.98 18.27 0 bottom
C264  10U_0603_6.3V6M  [C_0603]  59.93 16.21 180 bottom
C265  0.1U_0402_10V7K  [C_0402]  59.76 17.28 180 bottom
C266  10U_0402_6.3V6M  [C_0402]  223.34 39.77 90 top
C267  10U_0603_6.3V6M  [C_0603]  222.26 39.47 90 top
C268  0.01U_0402_16V  [C_0402]  224.34 45.45 0 top
C269  10U_0603_6.3V6M  [C_0603]  223.69 43.46 180 top
C270  0.1U_0402_10V7K  [C_0402]  223.69 42.19 180 top
C617  33P_0402_50V8J  [C_0402]  333.78 47.2 180 top
C618  33P_0402_50V8J  [C_0402]  333.78 46.31 180 top
C620  33P_0402_50V8J  [C_0402]  276.37 23.21 180 top
C621  0.047U_0402_16V4Z  [C_0402]  331.55 30.38 180 top
C622  22U_0402_6.3V6M  [C_0402]  333.38 48.33 90 top
C623  0.047U_0402_16V4Z  [C_0402]  331.55 31.26 180 top
C624  22U_0402_6.3V6M  [C_0402]  321.5 24.96 270 top
C625  0.047U_0402_16V4Z  [C_0402]  276.37 20.42 180 top
C627  0.047U_0402_16V4Z  [C_0402]  276.37 22.26 180 top
C628  33P_0402_50V8J  [C_0402]  276.37 21.3 180 top
C629  33P_0402_50V8J  [C_0402]  250.01 5.95 270 top
C630  33P_0402_50V8J  [C_0402]  253.82 5.95 270 top
C631  150U_B15G_6.3VM_R70M  [C_B15G]  262.06 16.5 0 bottom
C632  0.047U_0402_16V4Z  [C_0402]  252.87 5.95 270 top
C633  22U_0402_6.3V6M  [C_0402]  258.45 12.77 90 bottom
C634  0.047U_0402_16V4Z  [C_0402]  250.96 5.95 270 top
C635  22U_0402_6.3V6M  [C_0402]  333.75 31.72 0 top
C636  22U_0402_6.3V6M  [C_0402]  333.75 30.83 0 top
C637  22U_0402_6.3V6M  [C_0402]  333.75 29.94 0 top
C638  22U_0402_6.3V6M  [C_0402]  241.63 6.5 90 top
C639  22U_0402_6.3V6M  [C_0402]  242.52 6.5 90 top
C640  22U_0402_6.3V6M  [C_0402]  243.4 6.5 90 top
C641  150U_B15G_6.3VM_R70M  [C_B15G]  260.4 12.65 0 bottom
C2498  0.1U_0402_10V6K  [C_0402]  184.73 46.82 90 bottom
C2500  2200P_0402_25V7K  [C_0402]  140.47 130.71 90 bottom
C2502  2200P_0402_25V7K  [C_0402]  185.94 48.17 90 bottom
C2504  2200P_0402_25V7K  [C_0402]  187.79 47.21 180 bottom
C2505  2200P_0402_25V7K  [C_0402]  275.28 127.69 0 top
C2506  220P_0402_50V8J  [C_0402]  64.28 11.84 270 bottom
C2507  470P_0402_50V7K  [C_0402]  65.2 11.84 270 bottom
C2508  1U_0402_6.3V  [C_0402]  191.08 15.02 90 top
C2509  0.1U_0402_25V6K~D  [C_0402]  192.99 18.26 180 top
C2510  2200P_0402_25V7K  [C_0402]  189.18 43.94 270 bottom
C2511  2200P_0402_25V7K  [C_0402]  285.62 36.29 0 bottom
C2512  10U_0603_6.3V6M  [C_0603]  232.05 6.99 180 bottom
C2513  10U_0603_6.3V6M  [C_0603]  232.05 5.7 180 bottom
C2514  10U_0603_6.3V6M  [C_0603]  266.98 23.03 90 bottom
C2515  10U_0603_6.3V6M  [C_0603]  267.43 21.55 270 bottom
C2516  0.1U_0402_10V7K  [C_0402]  266.98 18.61 0 bottom
C2518  0.1U_0402_10V7K  [C_0402]  128.88 97.89 90 top
C2519  0.1U_0402_10V7K  [C_0402]  126.72 97.45 90 bottom
C2520  0.1U_0402_10V7K  [C_0402]  183.82 77.24 270 top
C2521  0.1U_0402_10V7K  [C_0402]  177.81 77.38 270 top
C2522  0.1U_0402_10V7K  [C_0402]  228.6 42.12 270 top
C2523  0.1U_0402_10V7K  [C_0402]  63.39 11.84 270 bottom
C2524  0.1U_0402_10V7K  [C_0402]  66.07 11.84 270 bottom
C2525  0.1U_0402_10V7K  [C_0402]  62.18 17.61 180 bottom
CA1  4.7U_0402_6.3V6M  [C_0402]  33.85 24.03 0 bottom
CA2  0.1U_0402_16V7K  [C_0402]  33.85 24.92 0 bottom
CA3  10U_0603_6.3V6M  [C_0603]  30.56 36.79 0 bottom
CA4  0.1U_0402_16V7K  [C_0402]  30.81 35.71 0 bottom
CA5  10U_0603_6.3V6M  [C_0603]  27.38 40.55 90 bottom
CA6  0.1U_0402_16V7K  [C_0402]  27.81 39.59 0 bottom
CA7  10U_0603_6.3V6M  [C_0603]  33.36 36.79 180 top
CA8  0.1U_0402_16V7K  [C_0402]  33.12 35.71 180 top
CA9  10U_0603_6.3V6M  [C_0603]  33.36 38 180 top
CA10  0.1U_0402_16V7K  [C_0402]  33.12 39.08 180 top
CA11  10P_0402_50V8J  [C_0402]  38.5 27.85 180 top
CA12  0.1U_0402_16V7K  [C_0402]  37.49 30.56 90 bottom
CA13  4.7U_0402_6.3V6M  [C_0402]  38.38 30.56 90 bottom
CA14  10U_0603_6.3V6M  [C_0603]  29.17 36.54 180 bottom
CA15  0.1U_0402_16V7K  [C_0402]  28.74 35.46 180 bottom
CA16  0.1U_0402_16V7K  [C_0402]  29.42 25.06 270 top
CA17  10U_0603_6.3V6M  [C_0603]  28.34 25.05 270 top
CA18  10P_0402_50V8J  [C_0402]  37.14 24.48 0 bottom
CA19  0.1U_0402_16V7K  [C_0402]  32.44 21.3 0 top
CA20  2.2U_0402_6.3V6M  [C_0402]  30.76 24.86 180 bottom
CA21  2.2U_0402_6.3V6M  [C_0402]  29.42 23.97 180 bottom
CA23  0.1U_0402_16V7K  [C_0402]  33.98 25 270 top
CA24  2.2U_0402_6.3V6M  [C_0402]  28.58 29.32 270 top
CA25  2.2U_0402_6.3V6M  [C_0402]  28.48 26.65 90 top
CA26  0.1U_0402_16V7K  [C_0402]  27.34 34.51 180 bottom
CA27  2.2U_0402_6.3V6M  [C_0402]  27.34 33.62 180 bottom
CA28  0.1U_0402_16V7K  [C_0402]  32.55 24.86 180 bottom
CA29  10U_0603_6.3V6M  [C_0603]  32.71 23.72 180 bottom
CA30  0.1U_0402_16V7K  [C_0402]  31.2 24.93 270 top
CA31  4.7U_0603_6.3V6M  [C_0603]  32.28 24.86 270 top
CA32  10U_0603_6.3V6M  [C_0603]  28.98 35.4 180 top
CA33  10U_0603_6.3V6M  [C_0603]  27.02 32.57 180 bottom
CA34  10P_0402_50V8J  [C_0402]  36.76 37.05 0 bottom
CA35  22P_0402_50V8J  [C_0402]  36.76 35.72 0 bottom
CA36  22P_0402_50V8J  [C_0402]  39.06 32.6 0 bottom
CA37  22P_0402_50V8J  [C_0402]  38.17 34.53 270 bottom
CA38  22P_0402_50V8J  [C_0402]  36.39 37.1 90 top
CA39  22P_0402_50V8J  [C_0402]  38.17 35.48 270 top
CA40  22P_0402_50V8J  [C_0402]  37.42 32.59 90 top
CA41  0.1U_0402_10V7K  [C_0402]  37.47 29.68 0 bottom
CA42  100P_0201_50V8J  [C_0201]  23.67 19.65 180 bottom
CA43  100P_0201_50V8J  [C_0201]  19.02 15.71 180 bottom
CA44  0.01U_0201_16V7  [C_0201]  17.79 24.24 270 top
CA45  680P_0402_50V8J  [C_0402]  27.82 19.48 270 bottom
CA46  680P_0402_50V8J  [C_0402]  28.71 17.74 90 bottom
CA47  330U_D2E_6.3VM_R25M  [C_D2E]  25.41 27.85 270 bottom
CA48  100P_0201_50V8J  [C_0201]  21.18 22.56 270 top
CA49  330U_D2E_6.3VM_R25M  [C_D2E]  20.65 27.85 270 bottom
CA50  100P_0201_50V8J  [C_0201]  21.12 24.12 180 top
CA51  0.01U_0201_16V7  [C_0201]  22.04 26.22 90 top
CA52  10U_0603_25V6M  [C_0603]  38.24 6.76 180 bottom
CA53  0.1U_0402_25V7K  [C_0402]  38.93 7.03 270 top
CA54  1000P_0402_50V7K  [C_0402]  38.16 4.97 0 top
CA55  10U_0603_25V6M  [C_0603]  29.16 4.86 180 top
CA56  0.1U_0402_25V7K  [C_0402]  30.87 6.18 90 bottom
CA57  1000P_0402_50V7K  [C_0402]  29.23 5.94 180 top
CA58  10U_0402_6.3V6M  [C_0402]  36.9 15.39 90 top
CA59  0.1U_0402_16V7K  [C_0402]  36.01 15.39 90 top
CA60  0.1U_0402_16V7K  [C_0402]  35.12 15.39 90 top
CA61  10U_0603_25V6M  [C_0603]  28.39 10.13 0 bottom
CA62  0.1U_0402_25V7K  [C_0402]  27.75 10.34 270 top
CA63  1000P_0402_50V7K  [C_0402]  28.64 10.34 270 top
CA64  10U_0402_6.3V6M  [C_0402]  36.51 14.96 0 bottom
CA65  0.1U_0402_16V7K  [C_0402]  36.51 15.85 0 bottom
CA66  1U_0402_16V6K  [C_0402]  27.87 8.1 0 top
CA67  .033U_0603_50V7  [C_0603]  39.52 6.01 45 bottom
CA68  .033U_0603_50V7  [C_0603]  36.13 4.04 180 top
CA69  .033U_0603_50V7  [C_0603]  32.39 4.14 0 top
CA70  .033U_0603_50V7  [C_0603]  27.69 7.02 0 top
CA71  1U_0402_16V6K  [C_0402]  38.37 8.74 180 bottom
CA74  0.1U_0402_16V7K  [C_0402]  33.85 15.01 90 bottom
CA77  10U_0402_6.3V6M  [C_0402]  35.25 13.51 270 bottom
CA78  0.1U_0402_16V7K  [C_0402]  34.37 13.51 270 bottom
CA79  10U_0603_25V6M  [C_0603]  33.73 5.62 90 bottom
CA80  0.1U_0402_25V7K  [C_0402]  34.81 5.92 90 bottom
CA81  1000P_0402_50V7K  [C_0402]  35.7 5.92 90 bottom
CA82  10U_0603_25V6M  [C_0603]  29.79 6.19 90 bottom
CA83  0.1U_0402_25V7K  [C_0402]  31.76 5.73 90 bottom
CA84  1000P_0402_50V7K  [C_0402]  32.65 5.73 90 bottom
CA85  10U_0402_6.3V6M  [C_0402]  35.31 25 270 top
CA87  330P_0402_50V7  [C_0402]  38.22 4.67 0 bottom
CA88  330P_0402_50V7  [C_0402]  36.19 2.99 180 top
CA89  330P_0402_50V7  [C_0402]  33.52 2.95 0 top
CA90  330P_0402_50V7  [C_0402]  31 3.35 270 top
CA91  680P_0402_50V8J  [C_0402]  18.37 16.8 270 top
CA92  680P_0402_50V8J  [C_0402]  18.25 19.58 90 top
CA254  1000P_0402_50V7K  [C_0402]  38.24 3.22 90 top
CA255  1000P_0402_50V7K  [C_0402]  35.84 4.22 180 bottom
CA256  1000P_0402_50V7K  [C_0402]  32.95 1.45 0 top
CA257  1000P_0402_50V7K  [C_0402]  29.98 3.35 270 top
CC1  0.22U_0201_6.3V  [C_0201]  217.14 120.68 0 bottom
CC2  0.22U_0201_6.3V  [C_0201]  215.87 121.57 0 bottom
CC3  0.22U_0201_6.3V  [C_0201]  216.7 123.6 0 bottom
CC4  0.22U_0201_6.3V  [C_0201]  214.98 124.62 0 bottom
CC5  0.22U_0201_6.3V  [C_0201]  216.25 125.13 0 bottom
CC6  0.22U_0201_6.3V  [C_0201]  214.98 126.59 0 bottom
CC7  0.22U_0201_6.3V  [C_0201]  216.25 127.58 0 bottom
CC8  0.22U_0201_6.3V  [C_0201]  214.92 128.56 0 bottom
CC9  0.22U_0201_6.3V  [C_0201]  153.93 171.86 90 bottom
CC10  0.22U_0201_6.3V  [C_0201]  155.14 173.77 90 bottom
CC11  0.22U_0201_6.3V  [C_0201]  156.34 171.87 90 bottom
CC12  0.22U_0201_6.3V  [C_0201]  157.78 173.76 90 bottom
CC13  0.22U_0201_6.3V  [C_0201]  217.14 120.11 0 bottom
CC14  0.22U_0201_6.3V  [C_0201]  215.87 121 0 bottom
CC15  0.22U_0201_6.3V  [C_0201]  216.7 123.03 0 bottom
CC16  0.22U_0201_6.3V  [C_0201]  214.98 124.05 0 bottom
CC17  0.22U_0201_6.3V  [C_0201]  216.25 125.7 0 bottom
CC18  0.22U_0201_6.3V  [C_0201]  214.98 126.02 0 bottom
CC19  0.22U_0201_6.3V  [C_0201]  216.25 126.91 0 bottom
CC20  0.22U_0201_6.3V  [C_0201]  214.92 127.98 0 bottom
CC21  0.22U_0201_6.3V  [C_0201]  153.04 171.86 90 bottom
CC22  0.22U_0201_6.3V  [C_0201]  154.25 173.77 90 bottom
CC23  0.22U_0201_6.3V  [C_0201]  155.45 171.87 90 bottom
CC24  0.22U_0201_6.3V  [C_0201]  156.86 173.76 90 bottom
CD1  1U_0402_6.3V6K~D  [C_0402]  173.12 60.39 270 top
CD2  1U_0402_6.3V6K~D  [C_0402]  164.66 60.43 270 top
CD3  1U_0402_6.3V6K~D  [C_0402]  179.27 60.63 0 top
CD4  1U_0402_6.3V6K~D  [C_0402]  179.27 59.74 0 top
CD5  10U_0603_6.3V6M~D  [C_0603]  150.01 60.57 270 top
CD6  10U_0603_6.3V6M~D  [C_0603]  143.91 60.57 270 top
CD7  10U_0603_6.3V6M~D  [C_0603]  139.91 60.57 270 top
CD8  10U_0603_6.3V6M~D  [C_0603]  139.47 51.23 90 top
CD9  10U_0603_6.3V6M~D  [C_0603]  179.03 61.71 0 top
CD10  10U_0603_6.3V6M~D  [C_0603]  179.03 62.92 0 top
CD11  220U_D7_2VM_R6M  [C_EEFSS0D221R]  163 74.07 0 top
CD12  1U_0402_6.3V6K~D  [C_0402]  178.4 49.07 180 top
CD13  10U_0603_6.3V6M~D  [C_0603]  179.46 50.77 0 top
CD14  10U_0603_6.3V6M~D  [C_0603]  178.84 47.99 180 top
CD15  10U_0603_6.3V6M~D  [C_0603]  179.46 52.04 0 top
CD16  0.1U_0402_16V7K~D  [C_0402]  176.63 62.85 180 top
CD17  2.2U_0603_6.3V6K~D  [C_0603]  176.87 63.93 180 top
CD18  0.1U_0402_16V7K~D  [C_0402]  154.45 51.35 90 top
CD19  1U_0402_6.3V6K~D  [C_0402]  130.19 47.69 270 top
CD20  1U_0402_6.3V6K~D  [C_0402]  163.21 47.69 270 top
CD21  1U_0402_6.3V6K~D  [C_0402]  135.96 40.01 90 top
CD22  1U_0402_6.3V6K~D  [C_0402]  114.44 39.41 270 top
CD23  10U_0603_6.3V6M~D  [C_0603]  140.48 38.47 90 top
CD24  10U_0603_6.3V6M~D  [C_0603]  150.2 47.74 270 top
CD25  10U_0603_6.3V6M~D  [C_0603]  153.82 47.74 270 top
CD26  10U_0603_6.3V6M~D  [C_0603]  143.21 38.47 90 top
CD27  10U_0603_6.3V6M~D  [C_0603]  180.3 48.18 0 top
CD28  10U_0603_6.3V6M~D  [C_0603]  180.3 49.39 0 top
CD29  0.1U_0402_16V7K~D  [C_0402]  154.44 39.42 0 top
CD30  1U_0402_6.3V6K~D  [C_0402]  180.54 47.1 0 top
CD31  1U_0402_6.3V6K~D  [C_0402]  180.54 46.21 0 top
CD32  1U_0402_6.3V6K~D  [C_0402]  179.67 39.99 180 top
CD33  220U_D7_2VM_R6M  [C_EEFSS0D221R]  159.11 74.07 180 top
CD34  0.1U_0402_16V7K~D  [C_0402]  177.57 45.75 180 top
CD35  2.2U_0603_6.3V6K~D  [C_0603]  178.26 46.79 180 top
CD69  0.1U_0402_16V7K~D  [C_0402]  137.43 52.26 270 top
CD70  10U_0603_6.3V6M~D  [C_0603]  153.44 60.57 270 top
CD71  10U_0603_6.3V6M~D  [C_0603]  150.31 51.21 90 top
CD72  10U_0603_6.3V6M~D  [C_0603]  151.91 51.23 90 top
CD73  10U_0603_6.3V6M~D  [C_0603]  140.92 52.23 90 top
CD74  1U_0402_6.3V6K~D  [C_0402]  168.49 52.32 270 top
CD75  1U_0402_6.3V6K~D  [C_0402]  124.92 51.35 90 top
CD76  1U_0402_6.3V6K~D  [C_0402]  135.47 51.35 90 top
CD77  1U_0402_6.3V6K~D  [C_0402]  157.94 52.32 270 top
CD78  1U_0402_6.3V6K~D  [C_0402]  130.13 60.51 270 top
CD79  1U_0402_6.3V6K~D  [C_0402]  119.53 60.45 270 top
CD80  1U_0402_6.3V6K~D  [C_0402]  158.01 38.58 90 top
CD81  1U_0402_6.3V6K~D  [C_0402]  168.42 38.52 90 top
CD82  1U_0402_6.3V6K~D  [C_0402]  171.97 45.07 270 top
CD83  1U_0402_6.3V6K~D  [C_0402]  120.2 49.31 0 top
CD84  10U_0603_6.3V6M~D  [C_0603]  140.66 47.78 270 top
CD85  10U_0603_6.3V6M~D  [C_0603]  146.38 45.05 0 top
CD86  10U_0603_6.3V6M~D  [C_0603]  151.59 38.47 90 top
CD87  10U_0603_6.3V6M~D  [C_0603]  139.26 47.78 270 top
CD88  10U_0603_6.3V6M~D  [C_0603]  179.98 38.91 180 top
CD89  10U_0603_6.3V6M~D  [C_0603]  179.98 36.37 180 top
CD90  10U_0603_6.3V6M~D  [C_0603]  179.98 37.58 180 top
CD91  0.1U_0402_16V7K~D  [C_0402]  138.18 49.77 270 top
CD92  0.1U_0402_16V7K~D  [C_0402]  139.07 49.77 270 top
CE1  1U_0402_6.3V  [C_0402]  318.69 7.17 270 top
CE3  0.1U_0402_16V4Z~D  [C_0402]  316.79 7.17 270 top
CE4  22P_0402_50V8J~D  [C_0402]  317.74 6.25 90 top
CE6  1U_0402_6.3V  [C_0402]  322.63 7.17 270 top
CE7  0.1U_0402_16V4Z~D  [C_0402]  321.74 7.17 270 top
CE9  0.1U_0402_16V4Z~D  [C_0402]  317.39 19.64 90 top
CE13  0.1U_0402_16V4Z~D  [C_0402]  322.75 16.48 0 top
CE14  0.1U_0402_16V4Z~D  [C_0402]  322.74 15.56 0 top
CE15  0.1U_0402_16V4Z~D  [C_0402]  322.74 14.67 0 top
CE16  0.1U_0402_16V4Z~D  [C_0402]  322.74 13.81 0 top
CE17  0.1U_0402_16V4Z~D  [C_0402]  322.75 12.92 0 top
CE18  0.1U_0402_16V4Z~D  [C_0402]  322.75 12.03 0 top
CE19  0.1U_0402_16V4Z~D  [C_0402]  103.69 25.41 0 bottom
CE20  22P_0402_50V8J~D  [C_0402]  101.09 25.52 90 bottom
CE22  4.7U_0603_10V  [C_0603]  104.29 30.17 270 bottom
CE24  0.1U_0402_16V4Z  [C_0402]  225.19 158.53 180 top
CE25  0.1U_0402_16V4Z  [C_0402]  188.74 24.06 90 top
CE27  0.1U_0402_16V7K  [C_0402]  309.11 15.82 0 top
CE28  0.1U_0402_10V7K  [C_0402]  289.87 8.3 270 top
CE29  0.1U_0402_10V7K  [C_0402]  297.05 25.91 90 top
CE30  0.1U_0402_10V7K  [C_0402]  303.02 25.91 90 top
CE31  1000P_0402_50V7K  [C_0402]  287.7 24.48 0 top
CE32  1000P_0402_50V7K  [C_0402]  309.17 23.05 270 top
CE33  0.1U_0402_10V7K  [C_0402]  287.45 11.08 0 top
CE34  0.047U_0402_16V4Z  [C_0402]  301.24 25.91 90 top
CE35  100P_0402_50V8J  [C_0402]  288.71 10.08 0 top
CE36  0.1U_0402_10V7K  [C_0402]  302.21 27.76 180 top
CE38  0.1U_0402_10V7K  [C_0402]  309.11 19.51 0 top
CE40  100P_0402_50V8J  [C_0402]  310.02 13.79 180 top
CE41  0.1U_0402_10V7K  [C_0402]  303.91 25.91 90 top
CE42  0.1U_0402_10V7K  [C_0402]  304.99 6.08 270 top
CE43  0.1U_0402_10V7K  [C_0402]  309.11 17.73 0 top
CE44  0.1U_0402_10V7K  [C_0402]  293.11 25.48 90 top
CE45  0.1U_0402_10V7K  [C_0402]  300.36 25.91 90 top
CE46  0.1U_0402_10V7K  [C_0402]  296.36 6.6 270 top
CE51  0.033U_0402_25V  [C_0402]  310.07 10.03 270 top
CE55  0.1U_0402_16V7K~D  [C_0402]  331.42 38.31 90 top
CE56  0.1U_0402_16V4Z  [C_0402]  327.68 42.07 180 top
CE57  10P_0402_50V8J  [C_0402]  314.74 7.56 0 top
CE58  10P_0402_50V8J  [C_0402]  313.34 19.72 90 top
CE59  10P_0402_50V8J  [C_0402]  319.64 7.17 270 top
CE60  10P_0402_50V8J  [C_0402]  320.85 7.17 270 top
CE61  0.1U_0402_16V4Z  [C_0402]  219.91 165.77 270 bottom
CE62  0.1U_0402_16V4Z  [C_0402]  313.83 55.73 180 top
CE63  0.1U_0402_16V7K~D  [C_0402]  315.4 54.26 0 top
CE64  0.1U_0402_16V7K  [C_0402]  103.69 26.32 0 bottom
CE65  10U_0402_6.3V6M  [C_0402]  103.69 27.21 0 bottom
CE79  0.1U_0402_10V6K  [C_0402]  144.8 166.61 0 top
CE80  4.7U_0805_10V4Z  [C_0805]  143.14 164.79 90 top
CE81  0.1U_0402_10V6K  [C_0402]  153.36 163.21 90 top
CE82  0.1U_0402_10V6K  [C_0402]  143.6 163.24 180 top
CE84  0.1U_0402_16V4Z  [C_0402]  44.38 47.4 0 bottom
CE85  0.1U_0402_16V4Z  [C_0402]  33.36 48.8 180 bottom
CE86  0.1U_0402_16V4Z  [C_0402]  284.54 31.15 0 bottom
CE87  0.1U_0402_16V4Z  [C_0402]  275.6 32.34 90 bottom
CE168  0.1U_0402_16V4Z  [C_0402]  301.9 35.4 180 top
CF4  22U_0603_6.3V6M  [C_0603]  107.58 61.03 270 top
CF5  22U_0805_6.3VAM  [C_0805]  290.39 74.06 180 top
CG1  0.1U_0201_6.3V6K  [C_0201]  197.4 104.07 90 bottom
CG2  1U_0402_6.3V6K  [C_0402]  234.78 114.17 180 top
CG3  1U_0402_6.3V6K  [C_0402]  234.5 116.05 0 top
CG4  1U_0402_6.3V6K  [C_0402]  234.69 110.19 0 top
CG5  4.7U_0603_6.3V6M  [C_0603]  233.94 117.13 0 top
CG6  10U_0603_6.3V6M  [C_0603]  232.23 118.08 270 top
CG7  22U_0805_6.3V6M  [C_0805]  240.78 108.08 0 top
CG8  0.22U_0201_6.3V  [C_0201]  206.98 132.3 0 top
CG9  0.22U_0201_6.3V  [C_0201]  206.98 132.87 0 top
CG10  0.22U_0201_6.3V  [C_0201]  205.71 133.32 0 top
CG11  4.7U_0603_6.3V6M  [C_0603]  225.75 107.03 90 top
CG12  10U_0603_6.3V6M  [C_0603]  227.15 102.27 90 top
CG13  1U_0402_6.3V6K  [C_0402]  243.15 109.56 90 top
CG14  4.7U_0603_6.3V6M  [C_0603]  233.94 118.33 0 top
CG16  0.22U_0201_6.3V  [C_0201]  205.71 133.89 0 top
CG17  1U_0402_6.3V6K  [C_0402]  226.75 106.95 0 top
CG18  1U_0402_6.3V6K  [C_0402]  225.45 102.84 180 top
CG19  1U_0402_6.3V6K  [C_0402]  238.9 108.57 270 top
CG20  4.7U_0603_6.3V6M  [C_0603]  222.96 118.78 180 top
CG21  10U_0603_6.3V6M  [C_0603]  221.56 119.98 0 top
CG22  0.22U_0201_6.3V  [C_0201]  206.98 134.27 0 top
CG23  1U_0402_6.3V6K  [C_0402]  236.86 110.13 90 top
CG24  22U_0603_6.3V6M  [C_0603]  217.47 106.71 0 top
CG25  0.22U_0201_6.3V  [C_0201]  206.98 134.84 0 top
CG26  0.22U_0201_6.3V  [C_0201]  205.77 135.1 0 top
CG27  0.22U_0201_6.3V  [C_0201]  205.77 135.67 0 top
CG28  0.22U_0201_6.3V  [C_0201]  206.98 135.99 0 top
CG29  0.22U_0201_6.3V  [C_0201]  206.98 136.56 0 top
CG30  0.22U_0201_6.3V  [C_0201]  205.77 136.87 0 top
CG31  0.22U_0201_6.3V  [C_0201]  205.77 137.45 0 top
CG32  0.22U_0201_6.3V  [C_0201]  206.98 137.7 0 top
CG33  0.22U_0201_6.3V  [C_0201]  206.98 138.27 0 top
CG34  0.1U_0201_6.3V6K  [C_0201]  218.98 110.46 0 top
CG35  0.22U_0201_6.3V  [C_0201]  205.9 139.22 0 top
CG36  0.22U_0201_6.3V  [C_0201]  205.9 139.8 0 top
CG40  0.1U_0402_10V7K  [C_0402]  242.97 112.49 0 top
CG42  4.7U_0402_6.3V6M  [C_0402]  234.78 111.28 180 top
CG43  4.7U_0402_6.3V6M  [C_0402]  234.78 113.29 180 top
CG47  0.1U_0402_10V7K  [C_0402]  229.05 116.22 90 top
CG48  0.1U_0402_10V7K  [C_0402]  231.14 107.92 0 top
CG49  0.1U_0402_10V7K  [C_0402]  228.16 116.22 90 top
CG51  0.1U_0402_10V7K  [C_0402]  228.42 108.69 270 top
CG53  0.1U_0402_10V7K  [C_0402]  233.83 107.92 180 top
CG54  0.1U_0402_16V7K  [C_0402]  229.69 88.79 90 top
CG55  22U_0603_6.3V6M  [C_0603]  204.03 105.21 270 top
CG56  0.1U_0402_16V4Z~D  [C_0402]  244.5 88.81 180 top
CG57  0.1U_0402_16V4Z~D  [C_0402]  246.71 103.49 270 top
CG58  0.1U_0402_16V4Z~D  [C_0402]  226.93 93.14 270 top
CG59  0.1U_0402_10V7K  [C_0402]  202.95 104.95 270 top
CG60  0.1U_0402_10V7K  [C_0402]  237.56 88.79 90 top
CG61  100P_0402_50V8J~D  [C_0402]  192.99 120.48 90 bottom
CG62  10U_0603_6.3V6M  [C_0603]  189.75 112.81 0 bottom
CG63  10U_0603_6.3V6M  [C_0603]  187.52 117.25 270 bottom
CG64  220P_0402_50V8J  [C_0402]  196.16 109.06 270 bottom
CG65  220P_0402_50V8J  [C_0402]  197.37 109.06 270 bottom
CG66  0.1U_0402_16V4Z  [C_0402]  211.83 105.57 0 bottom
CG75  22P_0402_50V8J  [C_0402]  212.23 118.73 270 bottom
CG76  22P_0402_50V8J  [C_0402]  212.23 115.65 90 bottom
CG78  820P_0402_25V7  [C_0402]  276.86 100.15 180 bottom
CG79  820P_0402_25V7  [C_0402]  276.54 103.85 0 bottom
CG80  22U_0603_6.3V6M  [C_0603]  283.54 84.8 180 bottom
CG81  22U_0603_6.3V6M  [C_0603]  285.25 111.98 270 bottom
CG82  22U_0603_6.3V6M  [C_0603]  278.51 84.8 180 bottom
CG83  10U_0402_6.3V4Z  [C_0402]  272.44 99.85 180 bottom
CG84  10U_0402_6.3V4Z  [C_0402]  278.66 99.85 180 bottom
CG85  10U_0402_6.3V4Z  [C_0402]  280.16 99.85 0 bottom
CG86  1U_0402_6.3V4Z  [C_0402]  278.72 118.84 180 bottom
CG87  1U_0402_6.3V4Z  [C_0402]  270.66 99.85 180 bottom
CG88  1U_0402_6.3V4Z  [C_0402]  272.63 103.85 180 bottom
CG89  1U_0402_6.3V4Z  [C_0402]  281.01 104.3 180 top
CG90  1U_0402_6.3V4Z  [C_0402]  273.62 90.65 0 top
CG91  1U_0402_6.3V4Z  [C_0402]  277.57 89.81 90 top
CG97  22U_0603_6.3V6M  [C_0603]  285.25 115.73 90 bottom
CG98  22U_0603_6.3V6M  [C_0603]  280.93 103.66 0 bottom
CG99  22U_0603_6.3V6M  [C_0603]  272.86 109.76 0 top
CG100  10U_0402_6.3V4Z  [C_0402]  279.59 118.84 0 bottom
CG101  10U_0402_6.3V4Z  [C_0402]  281.36 118.84 0 bottom
CG102  10U_0402_6.3V4Z  [C_0402]  270.85 103.85 180 bottom
CG103  1U_0402_6.3V4Z  [C_0402]  283.14 118.84 0 bottom
CG104  1U_0402_6.3V4Z  [C_0402]  279.4 84.87 0 bottom
CG105  1U_0402_6.3V4Z  [C_0402]  279.87 91.6 180 top
CG106  1U_0402_6.3V4Z  [C_0402]  281.64 99.28 180 top
CG113  820P_0402_25V7  [C_0402]  276.35 68.93 0 bottom
CG114  820P_0402_25V7  [C_0402]  263.09 58.57 90 bottom
CG115  22U_0603_6.3V6M  [C_0603]  285.19 75.15 270 bottom
CG116  22U_0603_6.3V6M  [C_0603]  285.19 71.91 270 bottom
CG117  22U_0603_6.3V6M  [C_0603]  272.49 100.93 0 bottom
CG118  10U_0402_6.3V4Z  [C_0402]  281.05 83.73 0 bottom
CG119  10U_0402_6.3V4Z  [C_0402]  279.27 83.73 0 bottom
CG120  10U_0402_6.3V4Z  [C_0402]  279.4 68.87 0 bottom
CG121  1U_0402_6.3V4Z  [C_0402]  272.31 68.93 180 bottom
CG122  1U_0402_6.3V4Z  [C_0402]  270.53 68.93 180 bottom
CG123  1U_0402_6.3V4Z  [C_0402]  263.09 56.79 90 bottom
CG124  1U_0402_6.3V4Z  [C_0402]  253.82 64.03 90 top
CG125  1U_0402_6.3V4Z  [C_0402]  262.77 58.38 90 top
CG126  1U_0402_6.3V4Z  [C_0402]  248.1 57.26 270 bottom
CG132  22U_0603_6.3V6M  [C_0603]  251.09 50.26 180 bottom
CG133  22U_0603_6.3V6M  [C_0603]  259.85 50.2 180 bottom
CG134  22U_0603_6.3V6M  [C_0603]  247.91 54.07 90 bottom
CG135  10U_0402_6.3V4Z  [C_0402]  249.34 64.99 270 top
CG136  10U_0402_6.3V4Z  [C_0402]  248.1 53.13 270 bottom
CG137  10U_0402_6.3V4Z  [C_0402]  248.55 53.26 270 top
CG138  1U_0402_6.3V4Z  [C_0402]  271.48 74.77 180 top
CG139  1U_0402_6.3V4Z  [C_0402]  257.31 62.53 270 top
CG140  1U_0402_6.3V4Z  [C_0402]  279.19 69.5 0 top
CG141  1U_0402_6.3V4Z  [C_0402]  262.45 55.48 270 top
CG148  820P_0402_25V7  [C_0402]  228.04 58.57 90 bottom
CG149  820P_0402_25V7  [C_0402]  232.1 58.38 90 bottom
CG150  22U_0603_6.3V6M  [C_0603]  233.18 53.5 270 top
CG151  22U_0603_6.3V6M  [C_0603]  242.17 51.63 180 top
CG152  22U_0603_6.3V6M  [C_0603]  227.08 64.04 90 top
CG153  10U_0402_6.3V4Z  [C_0402]  237.82 62.59 270 top
CG154  10U_0402_6.3V4Z  [C_0402]  245.82 61.61 90 top
CG155  10U_0402_6.3V4Z  [C_0402]  232.1 63.01 90 bottom
CG156  1U_0402_6.3V4Z  [C_0402]  233.12 64.6 90 top
CG157  1U_0402_6.3V4Z  [C_0402]  245.82 64.88 270 top
CG158  1U_0402_6.3V4Z  [C_0402]  245.82 56.18 270 top
CG159  1U_0402_6.3V4Z  [C_0402]  244.24 50.32 180 bottom
CG160  1U_0402_6.3V4Z  [C_0402]  235.16 50.32 180 bottom
CG161  1U_0402_6.3V4Z  [C_0402]  219.03 50.32 180 bottom
CG167  22U_0603_6.3V6M  [C_0603]  221.37 51.53 90 top
CG168  22U_0603_6.3V6M  [C_0603]  247.39 87.93 135 top
CG169  22U_0603_6.3V6M  [C_0603]  222.07 63.85 90 top
CG170  10U_0402_6.3V4Z  [C_0402]  218.89 61.77 270 top
CG171  10U_0402_6.3V4Z  [C_0402]  219.67 53.71 270 top
CG172  10U_0402_6.3V4Z  [C_0402]  232.1 64.79 90 bottom
CG173  1U_0402_6.3V4Z  [C_0402]  237.82 64.15 90 top
CG174  1U_0402_6.3V4Z  [C_0402]  242.13 58.46 270 top
CG175  1U_0402_6.3V4Z  [C_0402]  233.12 62.82 90 top
CG176  1U_0402_6.3V4Z  [C_0402]  222.25 62.57 270 top
CG183  10U_0603_6.3V6M  [C_0603]  191.27 120.36 180 bottom
CG184  10U_0603_6.3V6M  [C_0603]  228.35 56.93 180 top
CG185  10U_0603_6.3V6M  [C_0603]  233.51 57.5 270 top
CG186  10U_0603_6.3V6M  [C_0603]  191.97 75.47 180 top
CG187  10U_0603_6.3V6M  [C_0603]  191.97 76.8 180 top
CG188  10U_0603_6.3V6M  [C_0603]  206.83 69.69 90 top
CG189  10U_0603_6.3V6M  [C_0603]  269.95 85.95 0 top
CG190  10U_0603_6.3V6M  [C_0603]  205.24 101.51 180 top
CG191  10U_0603_6.3V6M  [C_0603]  199.14 96.49 180 top
CG192  1U_0402_6.3V4Z  [C_0402]  197.68 73.36 90 top
CG193  1U_0402_6.3V4Z  [C_0402]  204.26 96.34 0 top
CG194  1U_0402_6.3V4Z  [C_0402]  250.5 81.19 0 top
CG195  1U_0402_6.3V4Z  [C_0402]  200.87 101.51 180 top
CG196  1U_0402_6.3V4Z  [C_0402]  201.74 69.63 0 top
CG197  1U_0402_6.3V4Z  [C_0402]  194.65 68.87 180 top
CG198  1U_0402_6.3V4Z  [C_0402]  193.82 76.8 180 top
CG199  1U_0402_6.3V4Z  [C_0402]  204.47 93.25 0 top
CG200  1U_0402_6.3V4Z  [C_0402]  193.95 93.89 180 top
CG201  1U_0402_6.3V4Z  [C_0402]  202.62 93.12 0 top
CG202  1U_0402_6.3V4Z  [C_0402]  190.69 79.85 0 top
CG203  1U_0402_6.3V4Z  [C_0402]  196.17 83.34 180 bottom
CG204  1U_0402_6.3V4Z  [C_0402]  200.38 91.59 90 top
CG205  1U_0402_6.3V4Z  [C_0402]  195.92 94.14 180 top
CG206  1U_0402_6.3V4Z  [C_0402]  194.69 76.8 0 top
CG207  1U_0402_6.3V4Z  [C_0402]  204.97 87.34 0 bottom
CG208  1U_0402_6.3V4Z  [C_0402]  205.23 83.41 0 bottom
CG209  1U_0402_6.3V4Z  [C_0402]  204.11 87.34 180 bottom
CG210  1U_0402_6.3V4Z  [C_0402]  204.91 69.56 0 top
CG211  1U_0402_6.3V4Z  [C_0402]  201.95 96.55 180 top
CG212  1U_0402_6.3V4Z  [C_0402]  193.95 74.96 180 top
CG213  1U_0402_6.3V4Z  [C_0402]  198.75 73.44 0 top
CG214  1U_0402_6.3V4Z  [C_0402]  192.22 73.51 270 top
CG215  1U_0402_6.3V4Z  [C_0402]  194.71 101.76 180 top
CG216  10U_0603_6.3V6M  [C_0603]  197.11 68.74 180 top
CG217  10U_0603_6.3V6M  [C_0603]  191.4 91.54 270 top
CG218  10U_0603_6.3V6M  [C_0603]  226.21 87.8 45 top
CG219  10U_0603_6.3V6M  [C_0603]  228.23 64.87 270 bottom
CG220  22U_0603_6.3V6M  [C_0603]  270.96 100.93 180 bottom
CG221  22U_0603_6.3V6M  [C_0603]  285.25 109.57 270 bottom
CG222  22U_0603_6.3V6M  [C_0603]  236.36 50.26 0 bottom
CG223  22U_0603_6.3V6M  [C_0603]  242.2 50.26 180 bottom
CG224  22U_0603_6.3V6M  [C_0603]  282.27 68.8 0 bottom
CG225  22U_0603_6.3V6M  [C_0603]  285.12 79.85 90 bottom
CG226  22U_0603_6.3V6M  [C_0603]  263.22 52.8 270 bottom
CG227  22U_0603_6.3V6M  [C_0603]  257.31 50.2 180 bottom
CG228  22U_0603_6.3V6M  [C_0603]  260.87 50.2 0 bottom
CG230  0.1U_0402_10V7K  [C_0402]  225.13 109.76 180 top
CG231  10U_0603_6.3V6M  [C_0603]  218.64 117.7 90 top
CG232  47U_0805_6.3V6M~D  [C_0805]  220.16 117.86 90 top
CG233  0.1U_0402_10V7K  [C_0402]  246.72 91.41 180 top
CG234  0.1U_0402_10V7K  [C_0402]  235.81 108.54 270 top
CG235  0.1U_0402_10V7K  [C_0402]  234.9 108.54 270 top
CG236  0.1U_0402_10V7K  [C_0402]  226.4 110.65 180 top
CG237  0.1U_0402_10V7K  [C_0402]  226.93 97.31 0 top
CG238  0.1U_0402_10V7K  [C_0402]  226.61 114.29 180 top
CG239  22U_0603_6.3V6M  [C_0603]  224.29 116.24 90 top
CG240  0.1U_0402_16V7K  [C_0402]  192.02 105.38 180 bottom
CG241  0.1U_0402_16V4Z~D  [C_0402]  211.91 111.3 270 bottom
CG242  470U_X_2VY_R9M  [C_X]  268.8 61.5 270 bottom
CG243  10U_0603_6.3V6M  [C_0603]  202.83 83.6 0 bottom
CG244  470U_X_2VY_R9M  [C_X]  250.71 118.21 180 top
CG245  10U_0603_6.3V6M  [C_0603]  255.09 113 270 top
CG246  0.1U_0201_6.3V6K  [C_0201]  215.71 159.66 0 top
CG247  22U_0603_6.3V6M  [C_0603]  227 120.75 0 top
CG256  820P_0402_25V7  [C_0402]  195.54 84.23 180 bottom
CG265  820P_0402_25V7  [C_0402]  196.4 85.12 0 bottom
CG266  22U_0603_6.3V6M  [C_0603]  228.29 55.28 270 bottom
